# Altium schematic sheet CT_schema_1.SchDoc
size 656 x 463 mm
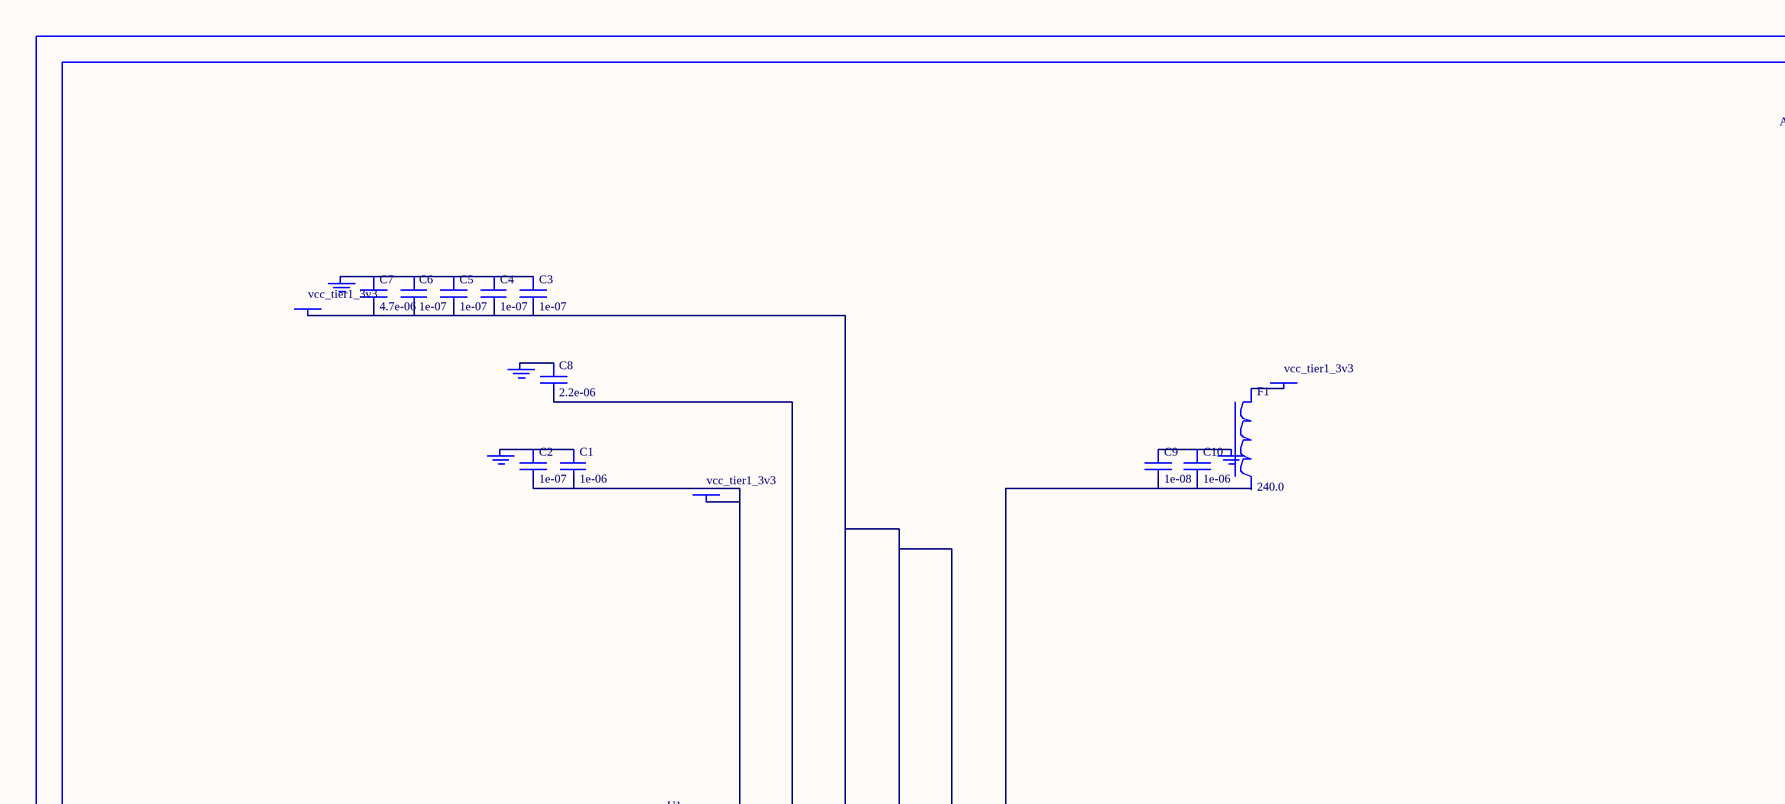
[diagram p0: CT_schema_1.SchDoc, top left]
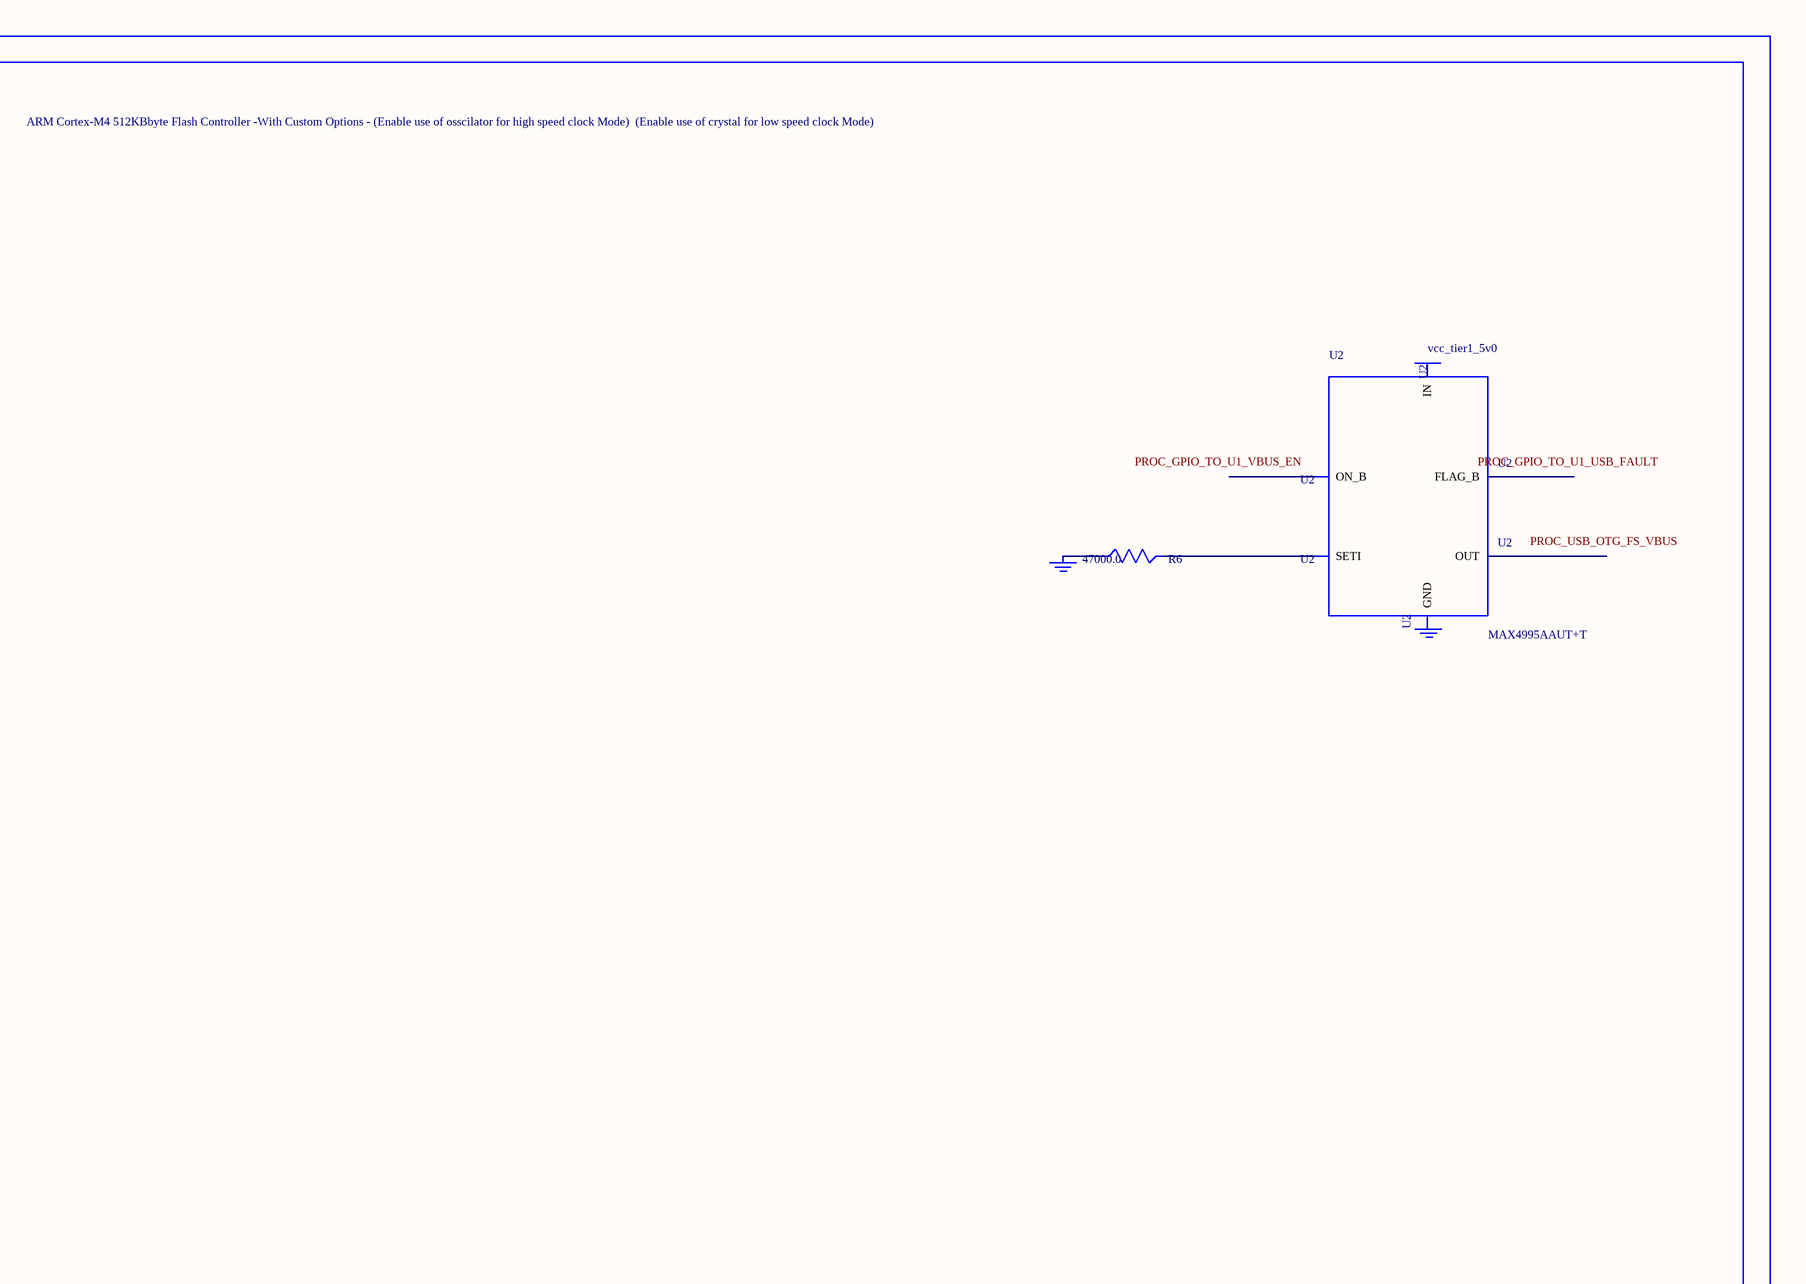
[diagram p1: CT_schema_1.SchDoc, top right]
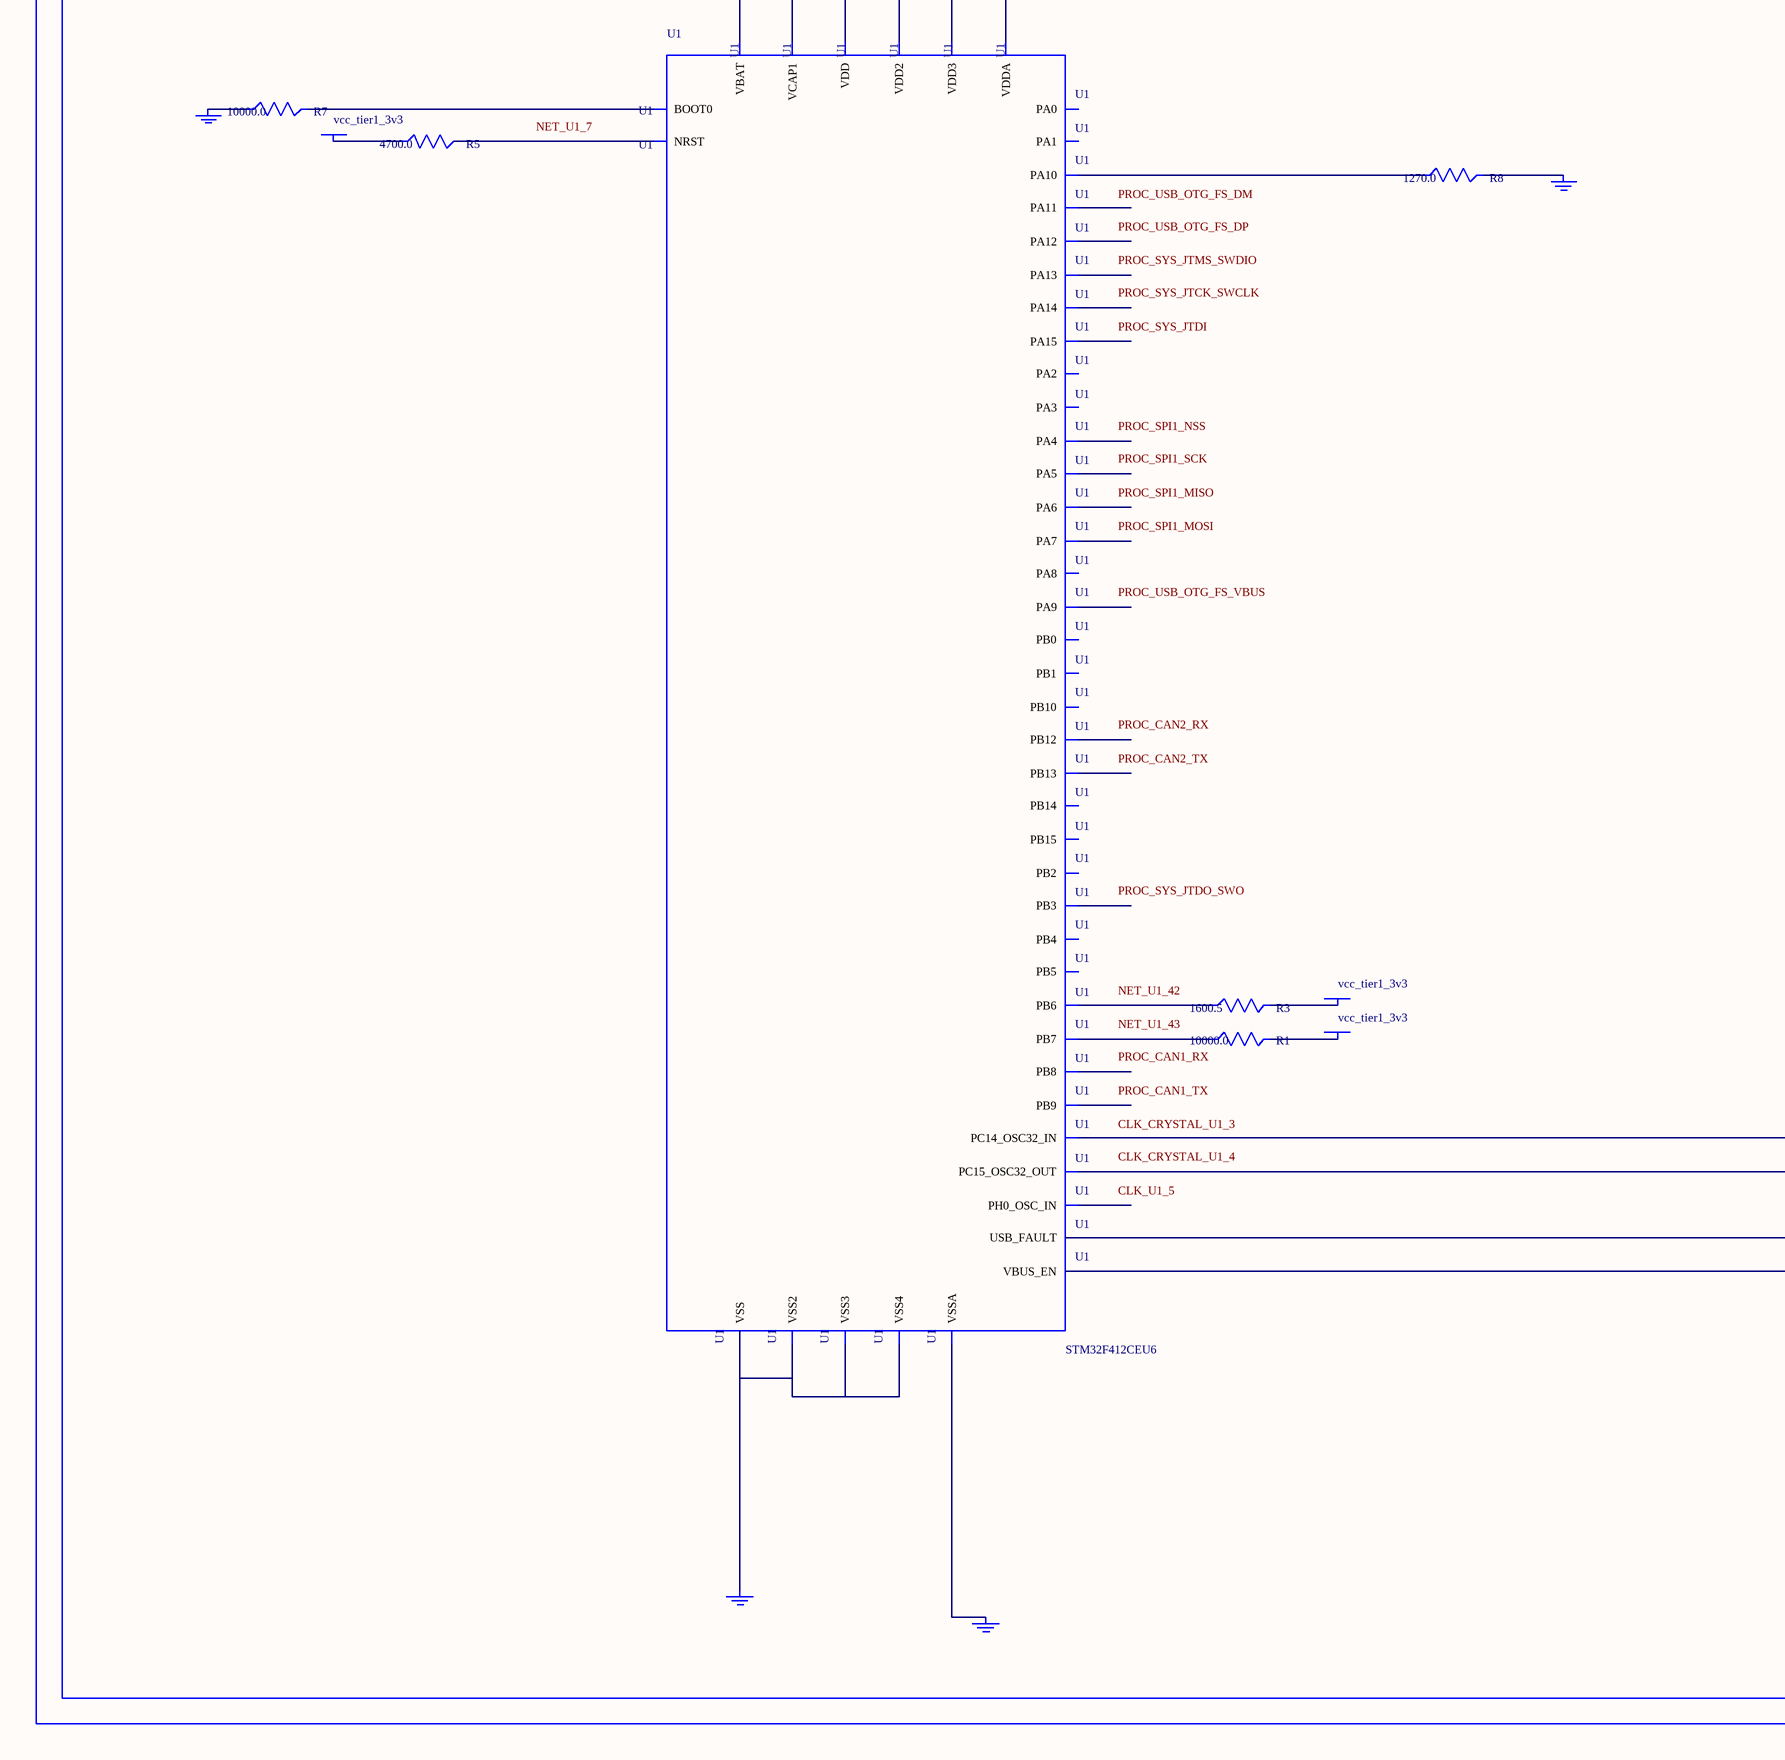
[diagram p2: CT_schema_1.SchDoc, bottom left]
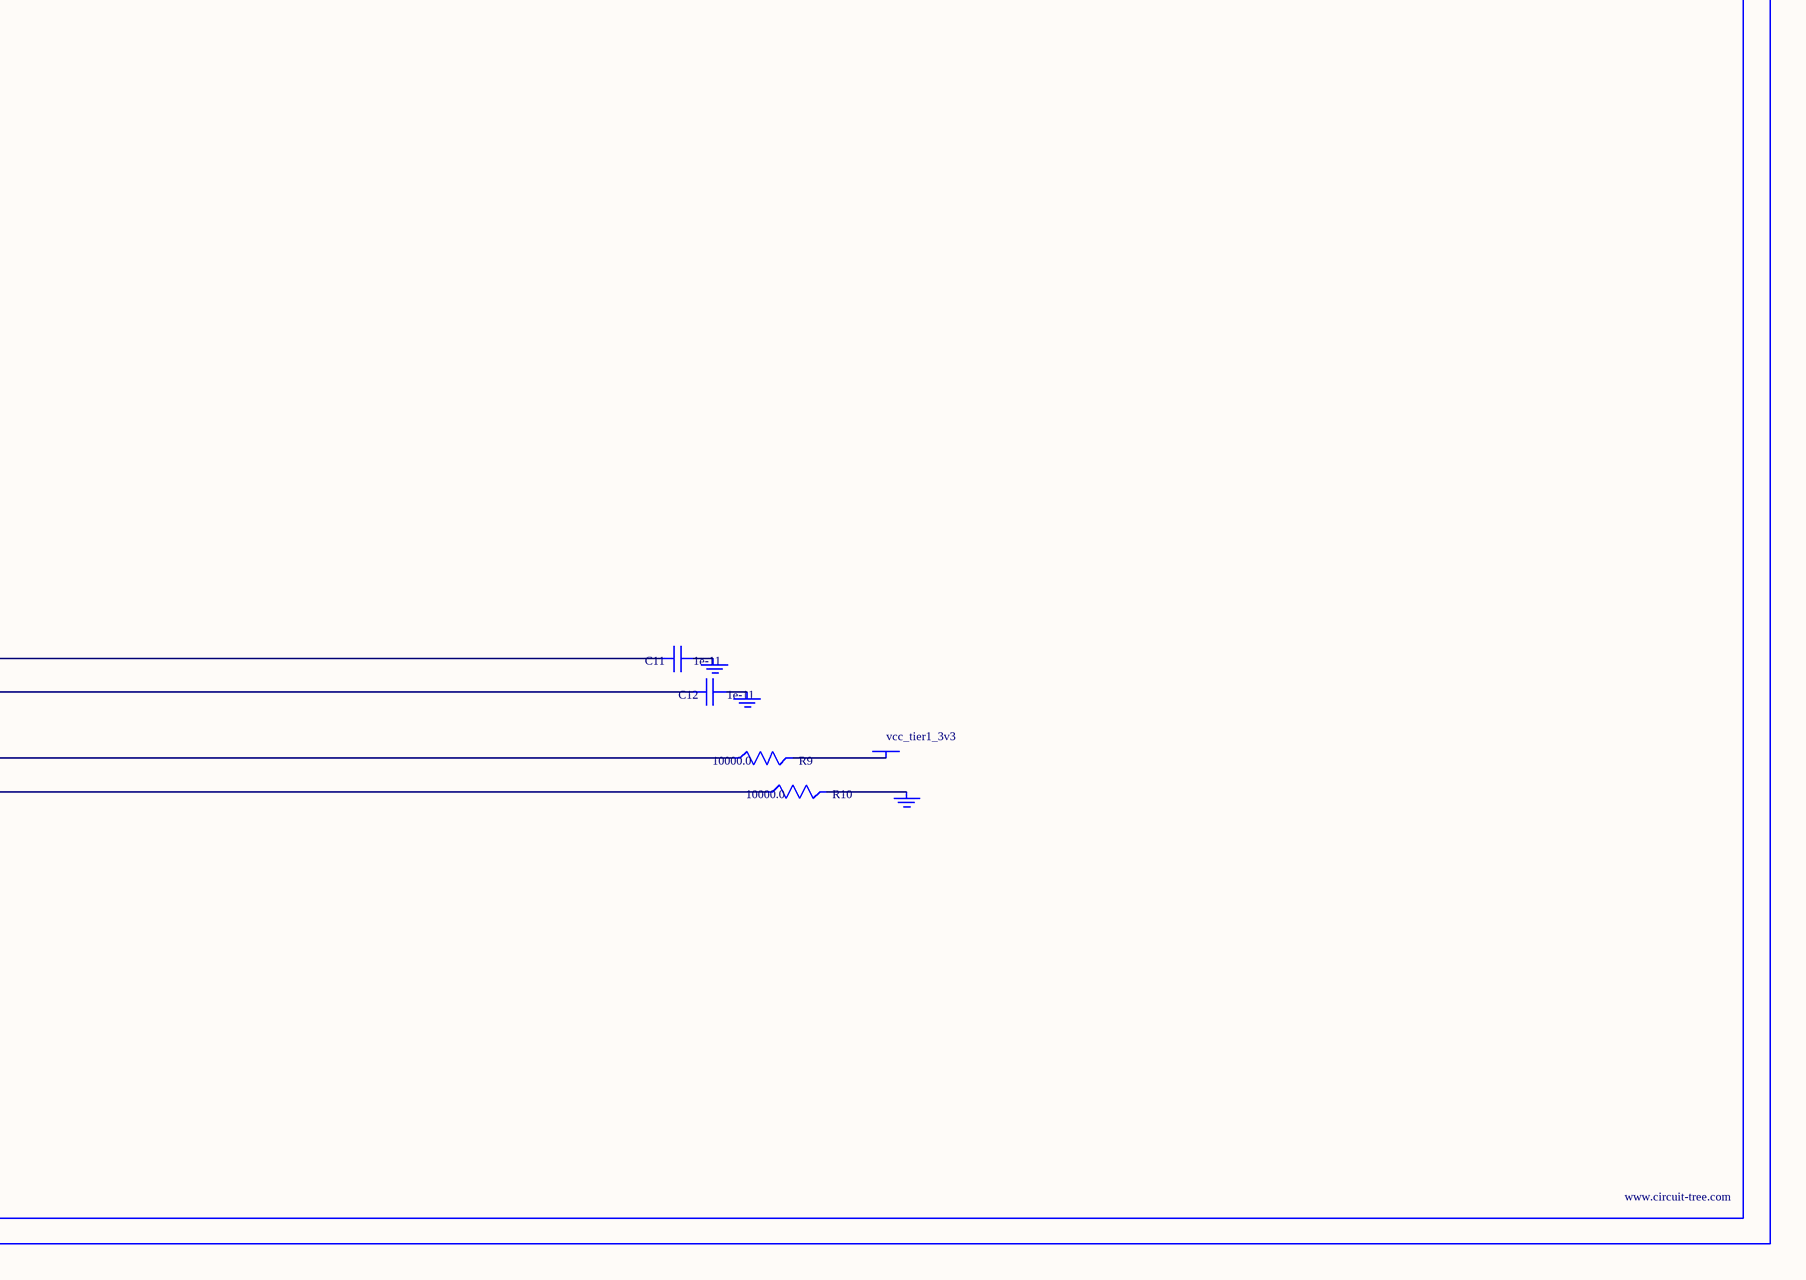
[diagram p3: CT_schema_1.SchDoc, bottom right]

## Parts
BORDER0  (no value)
C1  1e-06  [C0603]
C2  1e-07  [C0603]
C3  1e-07  [C0603]
C4  1e-07  [C0603]
C5  1e-07  [C0603]
C6  1e-07  [C0603]
C7  4.7e-06  [C0603]
C8  2.2e-06  [C0603]
C9  1e-08  [C0603]
C10  1e-06  [C0603]
C11  1e-11  [C0402]
C12  1e-11  [C0402]
F1  240.0  [L0603]
GND_INSTANCE_0_0  (no value)
GND_INSTANCE_0_1  (no value)
GND_INSTANCE_0_2  (no value)
GND_INSTANCE_0_3  (no value)
GND_INSTANCE_0_4  (no value)
GND_INSTANCE_0_5  (no value)
GND_INSTANCE_0_6  (no value)
GND_INSTANCE_0_7  (no value)
GND_INSTANCE_0_8  (no value)
GND_INSTANCE_0_9  (no value)
GND_INSTANCE_0_10  (no value)
GND_INSTANCE_0_11  (no value)
GND_INSTANCE_0_12  (no value)
POWER_INSTANCE_0_0  vcc_tier1_3v3
POWER_INSTANCE_0_1  vcc_tier1_3v3
POWER_INSTANCE_0_2  vcc_tier1_3v3
POWER_INSTANCE_0_3  vcc_tier1_3v3
POWER_INSTANCE_0_4  vcc_tier1_3v3
POWER_INSTANCE_0_5  vcc_tier1_3v3
POWER_INSTANCE_0_6  vcc_tier1_3v3
POWER_INSTANCE_0_7  vcc_tier1_5v0
R1  10000.0  [R0603]
R3  1600.5  [R0603]
R5  4700.0  [R0603]
R6  47000.0  [R0603]
R7  10000.0  [R0603]
R8  1270.0  [R0603]
R9  10000.0  [R0603]
R10  10000.0  [R0603]
U1  STM32F412CEU6  [UFQFPN48]
U2  MAX4995AAUT+T  [SOT-23-6]

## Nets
NetC1_1: C1.1 C2.1 GND_INSTANCE_0_0.0(GND)
NetC1_2: C1.2 C2.2 POWER_INSTANCE_0_0.0(PWR) U1.1(VBAT)
NetC3_1: C3.1 C4.1 C5.1 C6.1 C7.1 GND_INSTANCE_0_7.0(GND)
NetC3_2: C3.2 C4.2 C5.2 C6.2 C7.2 POWER_INSTANCE_0_3.0(PWR) U1.24(VDD) U1.36(VDD2) U1.48(VDD3)
NetC8_1: C8.1 GND_INSTANCE_0_6.0(GND)
NetC8_2: C8.2 U1.22(VCAP1)
NetC9_1: C9.1 C10.1 GND_INSTANCE_0_5.0(GND)
NetC9_2: C9.2 C10.2 U1.9(VDDA)
NetC11_1: C11.1 GND_INSTANCE_0_2.0(GND)
NetC11_2: C11.2 U1.3(PC14_OSC32_IN)
NetC12_1: C12.1 GND_INSTANCE_0_3.0(GND)
NetC12_2: C12.2 U1.4(PC15_OSC32_OUT)
NetF1_1: F1.1 POWER_INSTANCE_0_2.0(PWR)
NetGND_INSTANCE_0_1_0: GND_INSTANCE_0_1.0(GND) R10.2
NetGND_INSTANCE_0_4_0: GND_INSTANCE_0_4.0(GND) U1.8(VSSA)
NetGND_INSTANCE_0_8_0: GND_INSTANCE_0_8.0(GND) R8.2
NetGND_INSTANCE_0_9_0: GND_INSTANCE_0_9.0(GND) R7.1
NetGND_INSTANCE_0_10_0: GND_INSTANCE_0_10.0(GND) U1.23(VSS) U1.35(VSS2) U1.47(VSS3) U1.49(VSS4)
NetGND_INSTANCE_0_11_0: GND_INSTANCE_0_11.0(GND) R6.1
NetPOWER_INSTANCE_0_1_0: POWER_INSTANCE_0_1.0(PWR) R9.2
NetPOWER_INSTANCE_0_4_0: POWER_INSTANCE_0_4.0(PWR) R5.1
NetPOWER_INSTANCE_0_5_0: POWER_INSTANCE_0_5.0(PWR) R3.2
NetPOWER_INSTANCE_0_6_0: POWER_INSTANCE_0_6.0(PWR) R1.2
NetR1_1: R1.1 U1.43(PB7)
NetR3_1: R3.1 U1.42(PB6)
NetR5_2: R5.2 U1.7(NRST)
NetR6_2: R6.2 U2.3(SETI)
NetR7_2: R7.2 U1.44(BOOT0)
NetR8_1: R8.1 U1.31(PA10)
NetR9_1: R9.1 U1.6(USB_FAULT)
NetR10_1: R10.1 U1.2(VBUS_EN)

Not connected (* = marked no-connect by the designer): F1 2; GND_INSTANCE_0_12 0(GND); POWER_INSTANCE_0_7 0(PWR); U1 5(PH0_OSC_IN) 10(PA0) 11(PA1) 12(PA2) 13(PA3) 14(PA4) 15(PA5) 16(PA6) 17(PA7) 18(PB0) 19(PB1) 20(PB2) 21(PB10) 25(PB12) 26(PB13) 27(PB14) 28(PB15) 29(PA8) 30(PA9) 32(PA11) 33(PA12) 34(PA13) 37(PA14) 38(PA15) 39(PB3) 40(PB4) 41(PB5) 45(PB8) 46(PB9); U2 1(OUT) 2(GND) 4(ON_B) 5(IN) 6(FLAG_B)

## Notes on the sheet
- Labels drawn without touching a wire or pin: CLK_CRYSTAL_U1_3, CLK_CRYSTAL_U1_4, CLK_U1_5, NET_U1_7, NET_U1_42, NET_U1_43, PROC_CAN1_RX, PROC_CAN1_TX, PROC_CAN2_RX, PROC_CAN2_TX, PROC_GPIO_TO_U1_USB_FAULT, PROC_GPIO_TO_U1_VBUS_EN, PROC_SPI1_MISO, PROC_SPI1_MOSI, PROC_SPI1_NSS, PROC_SPI1_SCK, PROC_SYS_JTCK_SWCLK, PROC_SYS_JTDI, PROC_SYS_JTDO_SWO, PROC_SYS_JTMS_SWDIO, PROC_USB_OTG_FS_DM, PROC_USB_OTG_FS_DP, PROC_USB_OTG_FS_VBUS

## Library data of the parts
BORDER0 = BORDER_PAGE0
C1 C10 = C0603C105K3RACTU
C2-C6 = 06035C104K4Z2A
C7 = GRM188R6YA475KE15D
C8 = C0603C225K8RACTU
C9 = 06035C103K4Z2A
C11 C12 = C0402C100K3GACTU
F1 = Z0603C241ASMST
GND_INSTANCE_0_0-GND_INSTANCE_0_12 = GND
POWER_INSTANCE_0_0-POWER_INSTANCE_0_7 = PWR
R1 R7 R9 R10 = RC0603JR-0710KL
R3 = R3
R5 = RC0603JR-074K7L
R6 = RC0603JR-0747KL
R8 = RC0603FR-071K27L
